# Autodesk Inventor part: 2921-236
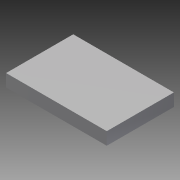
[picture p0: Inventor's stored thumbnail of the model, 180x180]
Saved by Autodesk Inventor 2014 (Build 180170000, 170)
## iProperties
Company: NHTSA/VRTC
Created: 2012-08
Part Number: 2921-236
Material: Steel, Mild
Document SubType Name: Modeling
Designer: Mike Vanvoorhis
Density: 7.86 g/cm^3
Mass: 289.805 g
Surface Area: 101.613 cm^2
Volume: 36.8709 cm^3
Project: CHILD SIDE IMPACT SLED
Description: HONEYCOMB FRAME BUMPER TUBE END CAP
Stock Number: PL 9.5 (3/8") x 50.8 (2") x 76.2 (3")
Appearance: Steel
Author: Dave Walker
Title: Honeycomb Frame Bumper Tube End Cap
Subject: Child Side Impacrt Sled
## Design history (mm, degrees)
sketch "Sketch1"
  geometry: L1 (0, 0)-(76.2, 0); L2 (76.2, 0)-(76.2, 9.525); L3 (76.2, 9.525)-(0, 9.525); L4 (0, 9.525)-(0, 0)
  constraints: 8 end point, 2 parallel, 1 horizontal, 1 perpendicular
  dimensions: "d0" = 76.2 distance of L3.end L2.end; "d1" = 9.525 distance of L2.end L1.end
extrude "Extrusion1" new body sketch "Sketch1" distance "d2" = 50.8; taper "d3" = 0 deg
body "Solid1"
